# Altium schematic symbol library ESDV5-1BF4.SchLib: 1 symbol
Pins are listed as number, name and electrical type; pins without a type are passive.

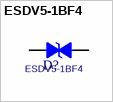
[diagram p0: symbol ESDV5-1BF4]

## ESDV5-1BF4
designator D?
footprint ST_0201B-F4
pins: 1, 2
